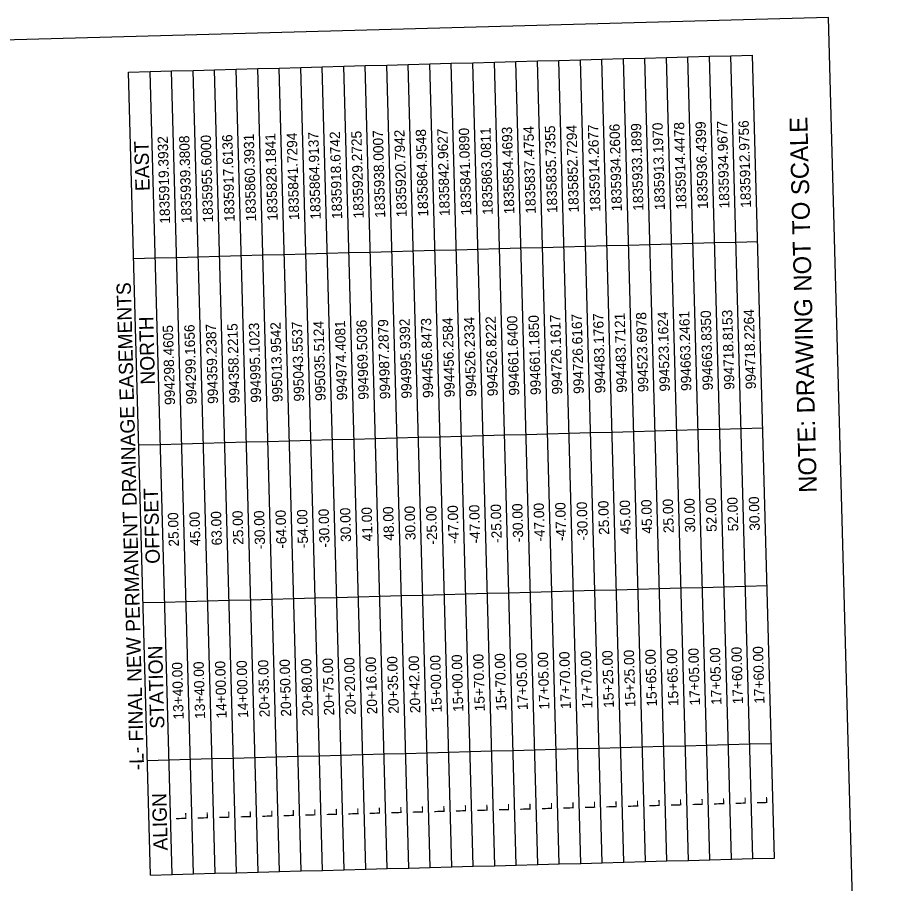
# Model space of a CAD drawing. Extents: x 1835096 to 1837089, y 993071 to 995976.
# Drawn here: x 1836175 to 1837037, y 995131 to 995976 of the extents above; entities that cross this region are included whole.
import ezdxf

# ---------------------------------------------------------------- set-up
doc = ezdxf.new("R2010")
doc.units = 0
for name, color, linetype in [('CTL Sheet Border CELL', 7, 'Continuous'), ('CTL Sheet Notes CELL', 7, 'Continuous'), ('CTL Sheet Table Cell', 7, 'Continuous'), ('CTL Sheet Text', 7, 'Continuous'), ('Sheet Data Field CELL', 7, 'Continuous')]:
    doc.layers.add(name, color=color, linetype=linetype)

msp = doc.modelspace()

# ---------------------------------------------------------------- linework, layer by layer
at = {"layer": 'CTL Sheet Border CELL'}
msp.add_lwpolyline([(1835140.76, 995926.46), (1835211.98, 993318.73), (1837037.37, 993368.58), (1836966.16, 995976.31)], close=True, dxfattribs=at)
at = {"layer": 'CTL Sheet Table Cell'}
for p, q in [((1836619.27, 995932.34), (1836640.26, 995932.91)), ((1836640.26, 995932.91), (1836661.25, 995933.48)), ((1836661.66, 995149.2), (1836640.26, 995932.91)), ((1836661.25, 995933.48), (1836682.24, 995934.06)), ((1836682.65, 995149.78), (1836661.25, 995933.48)), ((1836682.24, 995934.06), (1836703.24, 995934.63)), ((1836703.65, 995150.35), (1836682.24, 995934.06)), ((1836703.24, 995934.63), (1836724.23, 995935.2)), ((1836724.64, 995150.92), (1836703.24, 995934.63)), ((1836724.23, 995935.2), (1836745.22, 995935.78)), ((1836745.63, 995151.5), (1836724.23, 995935.2)), ((1836745.22, 995935.78), (1836766.21, 995936.35)), ((1836766.62, 995152.07), (1836745.22, 995935.78)), ((1836766.21, 995936.35), (1836787.21, 995936.92)), ((1836787.62, 995152.64), (1836766.21, 995936.35)), ((1836787.21, 995936.92), (1836808.2, 995937.5)), ((1836808.61, 995153.22), (1836787.21, 995936.92)), ((1836808.2, 995937.5), (1836829.19, 995938.07)), ((1836829.6, 995153.79), (1836808.2, 995937.5)), ((1836829.19, 995938.07), (1836850.18, 995938.64)), ((1836850.59, 995154.36), (1836829.19, 995938.07)), ((1836850.18, 995938.64), (1836871.17, 995939.22)), ((1836871.58, 995154.94), (1836850.18, 995938.64)), ((1836871.17, 995939.22), (1836892.17, 995939.79)), ((1836892.58, 995155.51), (1836871.17, 995939.22)), ((1836913.57, 995156.08), (1836892.17, 995939.79)), ((1836304.39, 995923.74), (1836325.38, 995924.31)), ((1836325.38, 995924.31), (1836346.37, 995924.88)), ((1836346.78, 995140.6), (1836325.38, 995924.31)), ((1836346.37, 995924.88), (1836367.36, 995925.46)), ((1836367.77, 995141.18), (1836346.37, 995924.88)), ((1836367.36, 995925.46), (1836388.35, 995926.03)), ((1836388.76, 995141.75), (1836367.36, 995925.46)), ((1836388.35, 995926.03), (1836409.35, 995926.6)), ((1836409.76, 995142.32), (1836388.35, 995926.03)), ((1836409.35, 995926.6), (1836430.34, 995927.18)), ((1836430.75, 995142.9), (1836409.35, 995926.6)), ((1836430.34, 995927.18), (1836451.33, 995927.75)), ((1836451.74, 995143.47), (1836430.34, 995927.18)), ((1836451.33, 995927.75), (1836472.32, 995928.32)), ((1836472.73, 995144.04), (1836451.33, 995927.75)), ((1836472.32, 995928.32), (1836493.31, 995928.9)), ((1836493.73, 995144.62), (1836472.32, 995928.32)), ((1836493.31, 995928.9), (1836514.31, 995929.47)), ((1836514.72, 995145.19), (1836493.31, 995928.9)), ((1836514.31, 995929.47), (1836535.3, 995930.04)), ((1836535.71, 995145.76), (1836514.31, 995929.47)), ((1836535.3, 995930.04), (1836556.29, 995930.62)), ((1836556.7, 995146.34), (1836535.3, 995930.04)), ((1836556.29, 995930.62), (1836577.28, 995931.19)), ((1836577.69, 995146.91), (1836556.29, 995930.62)), ((1836577.28, 995931.19), (1836598.28, 995931.76)), ((1836598.69, 995147.48), (1836577.28, 995931.19)), ((1836598.28, 995931.76), (1836619.27, 995932.34)), ((1836619.68, 995148.06), (1836598.28, 995931.76)), ((1836640.67, 995148.63), (1836619.27, 995932.34)), ((1836283.39, 995923.16), (1836304.39, 995923.74)), ((1836304.8, 995139.46), (1836283.39, 995923.16)), ((1836325.79, 995140.03), (1836304.39, 995923.74)), ((1836645.23, 995750.98), (1836666.22, 995751.55)), ((1836666.22, 995751.55), (1836687.21, 995752.12)), ((1836687.21, 995752.12), (1836708.21, 995752.7)), ((1836708.21, 995752.7), (1836729.2, 995753.27)), ((1836729.2, 995753.27), (1836750.19, 995753.84)), ((1836750.19, 995753.84), (1836771.18, 995754.42)), ((1836771.18, 995754.42), (1836792.17, 995754.99)), ((1836792.17, 995754.99), (1836813.17, 995755.56)), ((1836813.17, 995755.56), (1836834.16, 995756.14)), ((1836834.16, 995756.14), (1836855.15, 995756.71)), ((1836855.15, 995756.71), (1836876.14, 995757.28)), ((1836876.14, 995757.28), (1836897.13, 995757.86)), ((1836330.35, 995742.38), (1836351.34, 995742.95)), ((1836351.34, 995742.95), (1836372.33, 995743.53)), ((1836372.33, 995743.53), (1836393.32, 995744.1)), ((1836393.32, 995744.1), (1836414.31, 995744.67)), ((1836414.31, 995744.67), (1836435.31, 995745.24)), ((1836435.31, 995745.24), (1836456.3, 995745.82)), ((1836456.3, 995745.82), (1836477.29, 995746.39)), ((1836477.29, 995746.39), (1836498.28, 995746.96)), ((1836498.28, 995746.96), (1836519.28, 995747.54)), ((1836519.28, 995747.54), (1836540.27, 995748.11)), ((1836540.27, 995748.11), (1836561.26, 995748.68)), ((1836561.26, 995748.68), (1836582.25, 995749.26)), ((1836582.25, 995749.26), (1836603.24, 995749.83)), ((1836603.24, 995749.83), (1836624.24, 995750.4)), ((1836624.24, 995750.4), (1836645.23, 995750.98)), ((1836288.36, 995741.23), (1836309.35, 995741.81)), ((1836309.35, 995741.81), (1836330.35, 995742.38)), ((1836692.18, 995570.19), (1836713.17, 995570.77)), ((1836713.17, 995570.77), (1836734.17, 995571.34)), ((1836734.17, 995571.34), (1836755.16, 995571.91)), ((1836755.16, 995571.91), (1836776.15, 995572.49)), ((1836776.15, 995572.49), (1836797.14, 995573.06)), ((1836797.14, 995573.06), (1836818.13, 995573.63)), ((1836818.13, 995573.63), (1836839.13, 995574.21)), ((1836839.13, 995574.21), (1836860.12, 995574.78)), ((1836860.12, 995574.78), (1836881.11, 995575.35)), ((1836881.11, 995575.35), (1836902.1, 995575.93)), ((1836377.3, 995561.59), (1836398.29, 995562.17)), ((1836398.29, 995562.17), (1836419.28, 995562.74)), ((1836419.28, 995562.74), (1836440.28, 995563.31)), ((1836440.28, 995563.31), (1836461.27, 995563.89)), ((1836461.27, 995563.89), (1836482.26, 995564.46)), ((1836482.26, 995564.46), (1836503.25, 995565.03)), ((1836503.25, 995565.03), (1836524.24, 995565.61)), ((1836524.24, 995565.61), (1836545.24, 995566.18)), ((1836545.24, 995566.18), (1836566.23, 995566.75)), ((1836566.23, 995566.75), (1836587.22, 995567.33)), ((1836587.22, 995567.33), (1836608.21, 995567.9)), ((1836608.21, 995567.9), (1836629.2, 995568.47)), ((1836629.2, 995568.47), (1836650.2, 995569.05)), ((1836650.2, 995569.05), (1836671.19, 995569.62)), ((1836671.19, 995569.62), (1836692.18, 995570.19)), ((1836293.33, 995559.3), (1836314.32, 995559.87)), ((1836314.32, 995559.87), (1836335.31, 995560.45)), ((1836335.31, 995560.45), (1836356.31, 995561.02)), ((1836356.31, 995561.02), (1836377.3, 995561.59)), ((1836654.4, 995415.1), (1836675.39, 995415.68)), ((1836675.39, 995415.68), (1836696.39, 995416.25)), ((1836696.39, 995416.25), (1836717.38, 995416.82)), ((1836717.38, 995416.82), (1836738.37, 995417.4)), ((1836738.37, 995417.4), (1836759.36, 995417.97)), ((1836759.36, 995417.97), (1836780.35, 995418.54)), ((1836780.35, 995418.54), (1836801.35, 995419.12)), ((1836801.35, 995419.12), (1836822.34, 995419.69)), ((1836822.34, 995419.69), (1836843.33, 995420.26)), ((1836843.33, 995420.26), (1836864.32, 995420.84)), ((1836864.32, 995420.84), (1836885.32, 995421.41)), ((1836885.32, 995421.41), (1836906.31, 995421.98)), ((1836339.52, 995406.5), (1836360.51, 995407.08)), ((1836360.51, 995407.08), (1836381.5, 995407.65)), ((1836381.5, 995407.65), (1836402.5, 995408.22)), ((1836402.5, 995408.22), (1836423.49, 995408.8)), ((1836423.49, 995408.8), (1836444.48, 995409.37)), ((1836444.48, 995409.37), (1836465.47, 995409.94)), ((1836465.47, 995409.94), (1836486.46, 995410.52)), ((1836486.46, 995410.52), (1836507.46, 995411.09)), ((1836507.46, 995411.09), (1836528.45, 995411.66)), ((1836528.45, 995411.66), (1836549.44, 995412.24)), ((1836549.44, 995412.24), (1836570.43, 995412.81)), ((1836570.43, 995412.81), (1836591.42, 995413.38)), ((1836591.42, 995413.38), (1836612.42, 995413.96)), ((1836612.42, 995413.96), (1836633.41, 995414.53)), ((1836633.41, 995414.53), (1836654.4, 995415.1)), ((1836297.53, 995405.36), (1836318.53, 995405.93)), ((1836318.53, 995405.93), (1836339.52, 995406.5)), ((1836616.62, 995260.01), (1836637.61, 995260.59)), ((1836637.61, 995260.59), (1836658.61, 995261.16)), ((1836658.61, 995261.16), (1836679.6, 995261.73)), ((1836679.6, 995261.73), (1836700.59, 995262.31)), ((1836700.59, 995262.31), (1836721.58, 995262.88)), ((1836721.58, 995262.88), (1836742.57, 995263.45)), ((1836742.57, 995263.45), (1836763.57, 995264.03)), ((1836763.57, 995264.03), (1836784.56, 995264.6)), ((1836784.56, 995264.6), (1836805.55, 995265.17)), ((1836805.55, 995265.17), (1836826.54, 995265.75)), ((1836826.54, 995265.75), (1836847.53, 995266.32)), ((1836847.53, 995266.32), (1836868.53, 995266.89)), ((1836868.53, 995266.89), (1836889.52, 995267.47)), ((1836889.52, 995267.47), (1836910.51, 995268.04)), ((1836301.74, 995251.41), (1836322.73, 995251.99)), ((1836322.73, 995251.99), (1836343.72, 995252.56)), ((1836343.72, 995252.56), (1836364.71, 995253.13)), ((1836364.71, 995253.13), (1836385.71, 995253.71)), ((1836385.71, 995253.71), (1836406.7, 995254.28)), ((1836406.7, 995254.28), (1836427.69, 995254.85)), ((1836427.69, 995254.85), (1836448.68, 995255.43)), ((1836448.68, 995255.43), (1836469.68, 995256)), ((1836469.68, 995256), (1836490.67, 995256.57)), ((1836490.67, 995256.57), (1836511.66, 995257.15)), ((1836511.66, 995257.15), (1836532.65, 995257.72)), ((1836532.65, 995257.72), (1836553.64, 995258.29)), ((1836553.64, 995258.29), (1836574.64, 995258.87)), ((1836574.64, 995258.87), (1836595.63, 995259.44)), ((1836595.63, 995259.44), (1836616.62, 995260.01)), ((1836598.69, 995147.48), (1836619.68, 995148.06)), ((1836619.68, 995148.06), (1836640.67, 995148.63)), ((1836640.67, 995148.63), (1836661.66, 995149.2)), ((1836661.66, 995149.2), (1836682.65, 995149.78)), ((1836682.65, 995149.78), (1836703.65, 995150.35)), ((1836703.65, 995150.35), (1836724.64, 995150.92)), ((1836724.64, 995150.92), (1836745.63, 995151.5)), ((1836745.63, 995151.5), (1836766.62, 995152.07)), ((1836766.62, 995152.07), (1836787.62, 995152.64)), ((1836787.62, 995152.64), (1836808.61, 995153.22)), ((1836808.61, 995153.22), (1836829.6, 995153.79)), ((1836829.6, 995153.79), (1836850.59, 995154.36)), ((1836850.59, 995154.36), (1836871.58, 995154.94)), ((1836871.58, 995154.94), (1836892.58, 995155.51)), ((1836892.58, 995155.51), (1836913.57, 995156.08)), ((1836304.8, 995139.46), (1836325.79, 995140.03)), ((1836325.79, 995140.03), (1836346.78, 995140.6)), ((1836346.78, 995140.6), (1836367.77, 995141.18)), ((1836367.77, 995141.18), (1836388.76, 995141.75)), ((1836388.76, 995141.75), (1836409.76, 995142.32)), ((1836409.76, 995142.32), (1836430.75, 995142.9)), ((1836430.75, 995142.9), (1836451.74, 995143.47)), ((1836451.74, 995143.47), (1836472.73, 995144.04)), ((1836472.73, 995144.04), (1836493.73, 995144.62)), ((1836493.73, 995144.62), (1836514.72, 995145.19)), ((1836514.72, 995145.19), (1836535.71, 995145.76)), ((1836535.71, 995145.76), (1836556.7, 995146.34)), ((1836556.7, 995146.34), (1836577.69, 995146.91)), ((1836577.69, 995146.91), (1836598.69, 995147.48))]:
    msp.add_line(p, q, dxfattribs=at)

# ---------------------------------------------------------------- texts
at = {"layer": 'CTL Sheet Notes CELL'}
for s, p in [('EAST', (1836304.07, 995807.22)), ('-L- FINAL NEW PERMANENT DRAINAGE EASEMENTS', (1836298.5, 995241.95)), ('NORTH', (1836309.22, 995618.35)), ('OFFSET', (1836314, 995443.47)), ('STATION', (1836318.39, 995282.58)), ('ALIGN', (1836321.65, 995163.52))]:
    msp.add_text(s, height=14, rotation=91.56434, dxfattribs=at).set_placement(p)
at = {"layer": 'CTL Sheet Text'}
for s, p in [('1835934.2606', (1836764.78, 995787.38)), ('1835933.1899', (1836785.77, 995787.95)), ('1835913.1970', (1836806.76, 995788.53)), ('1835914.4478', (1836827.76, 995789.1)), ('1835936.4399', (1836848.75, 995789.67)), ('1835934.9677', (1836869.74, 995790.25)), ('1835912.9756', (1836890.73, 995790.82)), ('1835841.7294', (1836449.9, 995778.78)), ('1835864.9137', (1836470.89, 995779.35)), ('1835918.6742', (1836491.88, 995779.93)), ('1835929.2725', (1836512.87, 995780.5)), ('1835938.0007', (1836533.87, 995781.07)), ('1835920.7942', (1836554.86, 995781.65)), ('1835864.9548', (1836575.85, 995782.22)), ('1835842.9627', (1836596.84, 995782.79)), ('1835841.0890', (1836617.83, 995783.37)), ('1835863.0811', (1836638.83, 995783.94)), ('1835854.4693', (1836659.82, 995784.51)), ('1835837.4754', (1836680.81, 995785.09)), ('1835835.7355', (1836701.8, 995785.66)), ('1835852.7294', (1836722.79, 995786.23)), ('1835914.2677', (1836743.79, 995786.81)), ('1835919.3932', (1836323.94, 995775.34)), ('1835939.3808', (1836344.94, 995775.92)), ('1835955.6000', (1836365.93, 995776.49)), ('1835917.6136', (1836386.92, 995777.06)), ('1835860.3931', (1836407.91, 995777.64)), ('1835828.1841', (1836428.9, 995778.21)), ('994718.2264', (1836895.57, 995613.85)), ('994456.8473', (1836580.68, 995605.25)), ('994456.2584', (1836601.68, 995605.82)), ('994526.2334', (1836622.67, 995606.39)), ('994526.8222', (1836643.66, 995606.97)), ('994661.6400', (1836664.65, 995607.54)), ('994661.1850', (1836685.64, 995608.11)), ('994726.1617', (1836706.64, 995608.69)), ('994726.6167', (1836727.63, 995609.26)), ('994483.1767', (1836748.62, 995609.83)), ('994483.7121', (1836769.61, 995610.41)), ('994523.6978', (1836790.6, 995610.98)), ('994523.1624', (1836811.6, 995611.55)), ('994663.2461', (1836832.59, 995612.13)), ('994663.8350', (1836853.58, 995612.7)), ('994718.8153', (1836874.57, 995613.27)), ('994298.4605', (1836328.78, 995598.37)), ('994299.1656', (1836349.77, 995598.94)), ('994359.2387', (1836370.76, 995599.52)), ('994358.2215', (1836391.75, 995600.09)), ('994995.1023', (1836412.75, 995600.66)), ('995013.9542', (1836433.74, 995601.23)), ('995043.5537', (1836454.73, 995601.81)), ('995035.5124', (1836475.72, 995602.38)), ('994974.4081', (1836496.71, 995602.95)), ('994969.5036', (1836517.71, 995603.53)), ('994987.2879', (1836538.7, 995604.1)), ('994995.9392', (1836559.69, 995604.67)), ('-30.00', (1836668.56, 995464.4)), ('-47.00', (1836689.55, 995464.97)), ('-47.00', (1836710.55, 995465.54)), ('-30.00', (1836731.54, 995466.12)), ('25.00', (1836752.39, 995471.65)), ('45.00', (1836773.39, 995472.22)), ('45.00', (1836794.38, 995472.8)), ('25.00', (1836815.37, 995473.37)), ('30.00', (1836836.36, 995473.94)), ('52.00', (1836857.35, 995474.52)), ('52.00', (1836878.35, 995475.09)), ('30.00', (1836899.34, 995475.66)), ('25.00', (1836332.55, 995460.18)), ('45.00', (1836353.54, 995460.76)), ('63.00', (1836374.53, 995461.33)), ('25.00', (1836395.53, 995461.9)), ('-30.00', (1836416.65, 995457.52)), ('-64.00', (1836437.65, 995458.09)), ('-54.00', (1836458.64, 995458.66)), ('-30.00', (1836479.63, 995459.24)), ('30.00', (1836500.49, 995464.77)), ('41.00', (1836521.48, 995465.34)), ('48.00', (1836542.47, 995465.92)), ('30.00', (1836563.46, 995466.49)), ('-25.00', (1836584.59, 995462.1)), ('-47.00', (1836605.58, 995462.68)), ('-47.00', (1836626.58, 995463.25)), ('-25.00', (1836647.57, 995463.82)), ('15+70.00', (1836631.05, 995299.39)), ('15+70.00', (1836652.04, 995299.96)), ('17+05.00', (1836673.04, 995300.54)), ('17+05.00', (1836694.03, 995301.11)), ('17+70.00', (1836715.02, 995301.68)), ('17+70.00', (1836736.01, 995302.26)), ('15+25.00', (1836757, 995302.83)), ('15+25.00', (1836778, 995303.4)), ('15+65.00', (1836798.99, 995303.98)), ('15+65.00', (1836819.98, 995304.55)), ('17+05.00', (1836840.97, 995305.12)), ('17+05.00', (1836861.97, 995305.7)), ('17+60.00', (1836882.96, 995306.27)), ('17+60.00', (1836903.95, 995306.84)), ('13+40.00', (1836337.16, 995291.36)), ('13+40.00', (1836358.15, 995291.94)), ('14+00.00', (1836379.15, 995292.51)), ('14+00.00', (1836400.14, 995293.08)), ('20+35.00', (1836421.13, 995293.66)), ('20+50.00', (1836442.12, 995294.23)), ('20+80.00', (1836463.11, 995294.8)), ('20+75.00', (1836484.11, 995295.38)), ('20+20.00', (1836505.1, 995295.95)), ('20+16.00', (1836526.09, 995296.52)), ('20+35.00', (1836547.08, 995297.1)), ('20+42.00', (1836568.07, 995297.67)), ('15+00.00', (1836589.07, 995298.24)), ('15+00.00', (1836610.06, 995298.82)), ('L', (1836654.73, 995201.73)), ('L', (1836675.72, 995202.3)), ('L', (1836696.71, 995202.87)), ('L', (1836717.7, 995203.45)), ('L', (1836738.7, 995204.02)), ('L', (1836759.69, 995204.59)), ('L', (1836780.68, 995205.17)), ('L', (1836801.67, 995205.74)), ('L', (1836822.66, 995206.31)), ('L', (1836843.66, 995206.88)), ('L', (1836864.65, 995207.46)), ('L', (1836885.64, 995208.03)), ('L', (1836906.63, 995208.6)), ('L', (1836339.84, 995193.13)), ('L', (1836360.84, 995193.7)), ('L', (1836381.83, 995194.27)), ('L', (1836402.82, 995194.85)), ('L', (1836423.81, 995195.42)), ('L', (1836444.8, 995195.99)), ('L', (1836465.8, 995196.57)), ('L', (1836486.79, 995197.14)), ('L', (1836507.78, 995197.71)), ('L', (1836528.77, 995198.29)), ('L', (1836549.77, 995198.86)), ('L', (1836570.76, 995199.43)), ('L', (1836591.75, 995200.01)), ('L', (1836612.74, 995200.58)), ('L', (1836633.73, 995201.15))]:
    msp.add_text(s, height=10, rotation=91.56434, dxfattribs=at).set_placement(p)
at = {"layer": 'Sheet Data Field CELL'}
msp.add_text('NOTE: DRAWING NOT TO SCALE', height=17.3913, rotation=91.45909, dxfattribs=at).set_placement((1836954.98, 995512.83))

doc.saveas('drawing.dxf')
